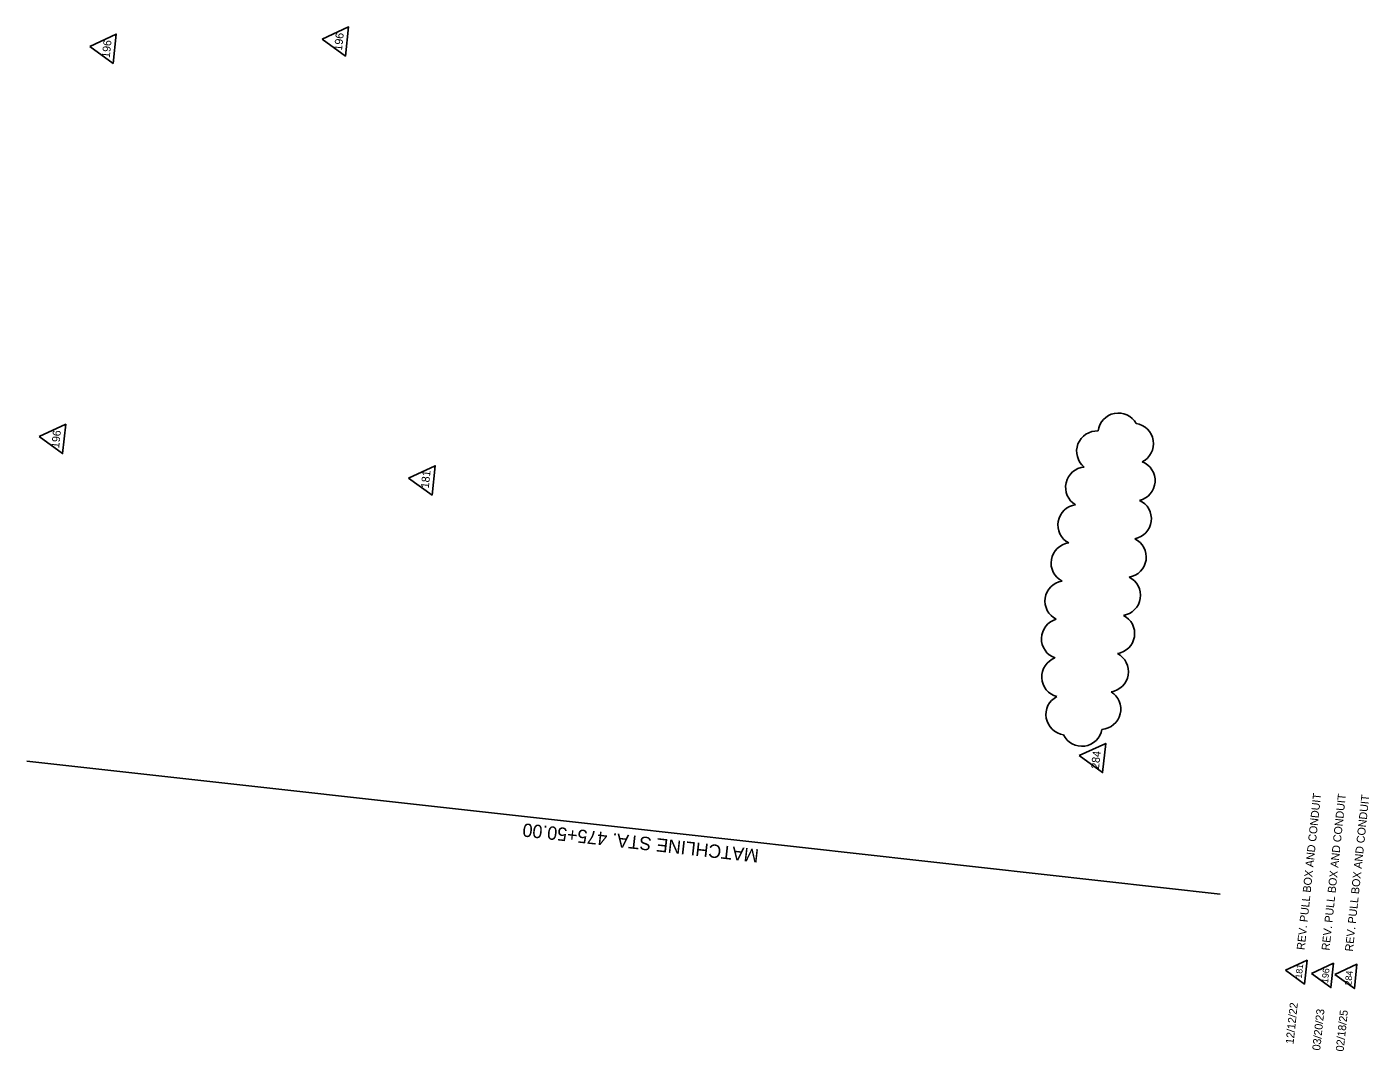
# Model space of a CAD drawing. Extents: x 930797 to 931706, y 623569 to 624777.
# Drawn here: x 930797 to 931602, y 623569 to 624184 of the extents above; entities that cross this region are included whole.
import ezdxf

# ---------------------------------------------------------------- set-up
doc = ezdxf.new("R2010")
doc.units = 0
for name, color, linetype in [('Cloud_dp', 7, 'Continuous'), ('MatchLines_dp', 7, 'Continuous'), ('TextMinor', 7, 'Continuous')]:
    doc.layers.add(name, color=color, linetype=linetype)

msp = doc.modelspace()

# ---------------------------------------------------------------- linework, layer by layer
at = {"layer": 'Cloud_dp'}
for points in [[(930974.02, 624176.22), (930988.07, 624166.07), (930989.93, 624183.62)], [(930834.72, 624171.87), (930848.77, 624161.72), (930850.63, 624179.27)], [(930804.4, 623937.83), (930818.46, 623927.67), (930820.32, 623945.22)], [(931025.99, 623912.91), (931040.04, 623902.76), (931041.9, 623920.31)], [(931428.11, 623746.45), (931442.17, 623736.29), (931444.03, 623753.84)], [(931551.78, 623617.73), (931563.24, 623609.45), (931564.75, 623623.76)], [(931567.43, 623615.75), (931579.09, 623607.33), (931580.63, 623621.89)], [(931581.48, 623615.15), (931593.14, 623606.73), (931594.69, 623621.29)]]:
    msp.add_lwpolyline(points, close=True, dxfattribs=at)
for centre, radius, start, end in [((931451.57, 623939.82), 12.17, 28.50861, 173.50861), ((931438.75, 623929.05), 12.17, 86.52961, 231.52961), ((931460.49, 623933.6), 12.17, 296.58789, 81.58789), ((931432.14, 623907.4), 12.17, 94.5503, 239.5503), ((931461.47, 623911.4), 12.17, 283.47115, 68.47115), ((931427.5, 623884.83), 12.17, 97.20652, 242.20652), ((931459.25, 623888.49), 12.17, 280.45095, 65.45095), ((931456.16, 623865.57), 12.17, 279.18327, 64.18327), ((931423.45, 623862.01), 12.17, 97.66213, 242.66213), ((931452.75, 623842.63), 12.17, 278.91585, 63.91585), ((931419.75, 623839.18), 12.17, 98.93233, 243.93233), ((931417.67, 623816.53), 12.17, 105.54801, 250.54801), ((931449.22, 623819.71), 12.17, 278.58489, 63.58489), ((931417.8, 623793.63), 12.17, 110.14198, 255.14198), ((931445.52, 623796.83), 12.17, 278.04615, 63.04615), ((931420.33, 623771.09), 12.17, 117.64182, 262.64182), ((931440.93, 623774.37), 12.17, 273.8335, 58.8335), ((931429.75, 623764.24), 12.16, 205.45006, 350.45006)]:
    msp.add_arc(centre, radius, start, end, dxfattribs=at)
at = {"layer": 'MatchLines_dp'}
msp.add_lwpolyline([(931512.58, 623663.44), (931154.79, 623703.3), (930797.01, 623743.17)], dxfattribs=at)

# ---------------------------------------------------------------- texts
at = {"layer": 'Cloud_dp'}
for s, height, p in [('196', 4.799, (930846.68, 624164.8)), ('196', 4.799, (930985.97, 624169.15)), ('196', 4.799, (930816.36, 623930.75)), ('181', 4.799, (931038.03, 623906.63)), ('284', 4.799, (931439.96, 623738.33)), ('181', 3.911, (931561.59, 623612.61)), ('196', 3.981, (931577.35, 623609.88)), ('284', 3.981, (931591.31, 623608.41))]:
    msp.add_text(s, height=height, rotation=83.95697, dxfattribs=at).set_placement(p)
at = {"layer": 'MatchLines_dp'}
msp.add_text('MATCHLINE STA. 475+50.00', height=8, rotation=173.6425, dxfattribs=at).set_placement((931236.35, 623690.19))
at = {"layer": 'TextMinor'}
for s, p in [('REV. PULL BOX AND CONDUIT', (931563.28, 623629.71)), ('REV. PULL BOX AND CONDUIT', (931578.19, 623629.41)), ('REV. PULL BOX AND CONDUIT', (931592.24, 623628.81)), ('12/12/22', (931556.65, 623573.25)), ('03/20/23', (931572.63, 623569.43)), ('02/18/25', (931586.69, 623568.82))]:
    msp.add_text(s, height=4.8, rotation=83.95697, dxfattribs=at).set_placement(p)

doc.saveas('drawing.dxf')
